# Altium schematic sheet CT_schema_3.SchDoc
size 522 x 390 mm
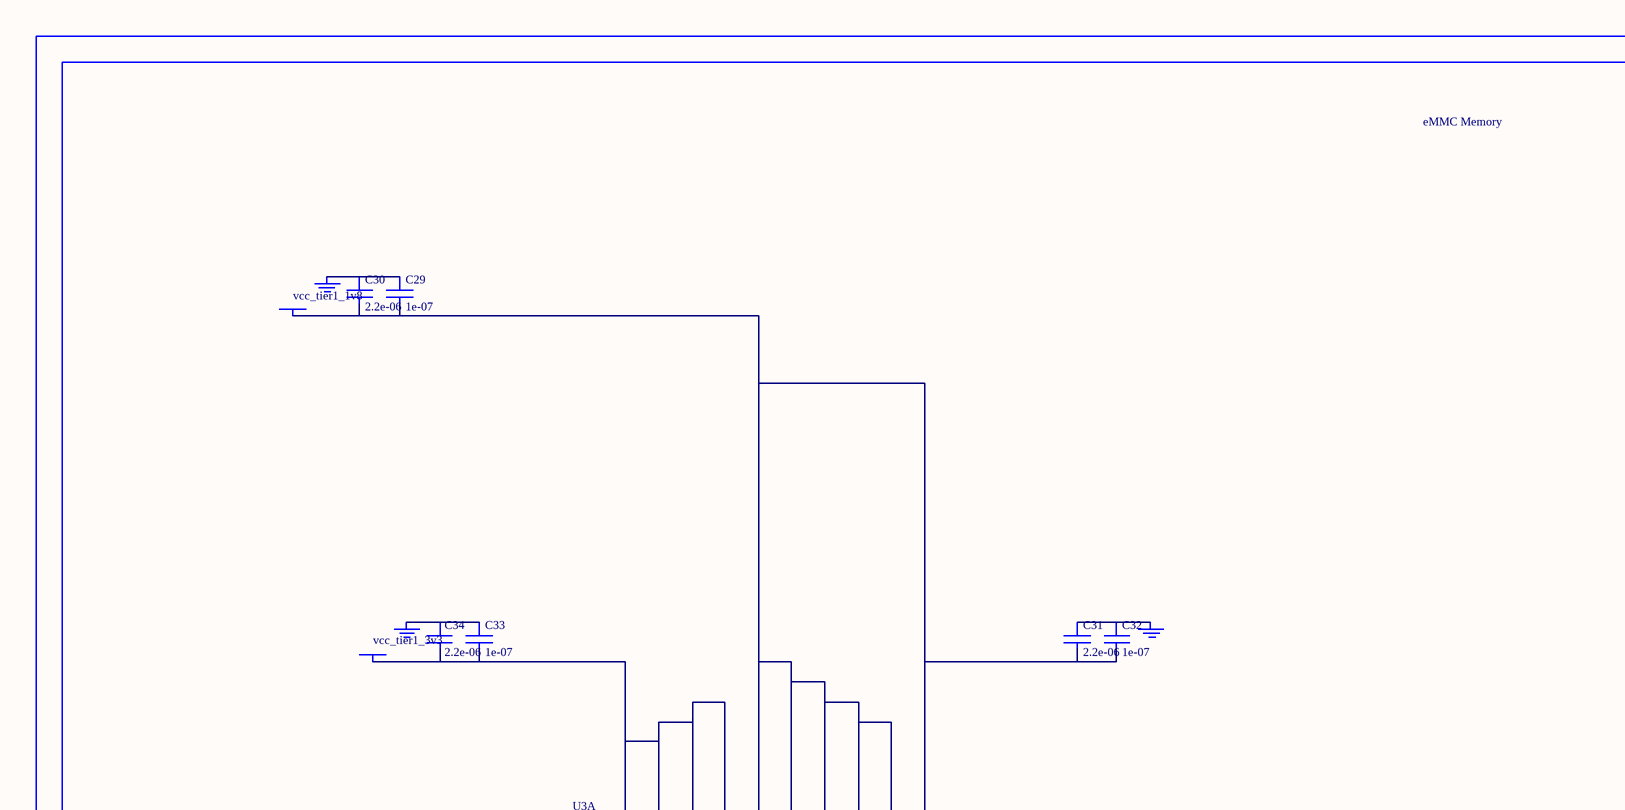
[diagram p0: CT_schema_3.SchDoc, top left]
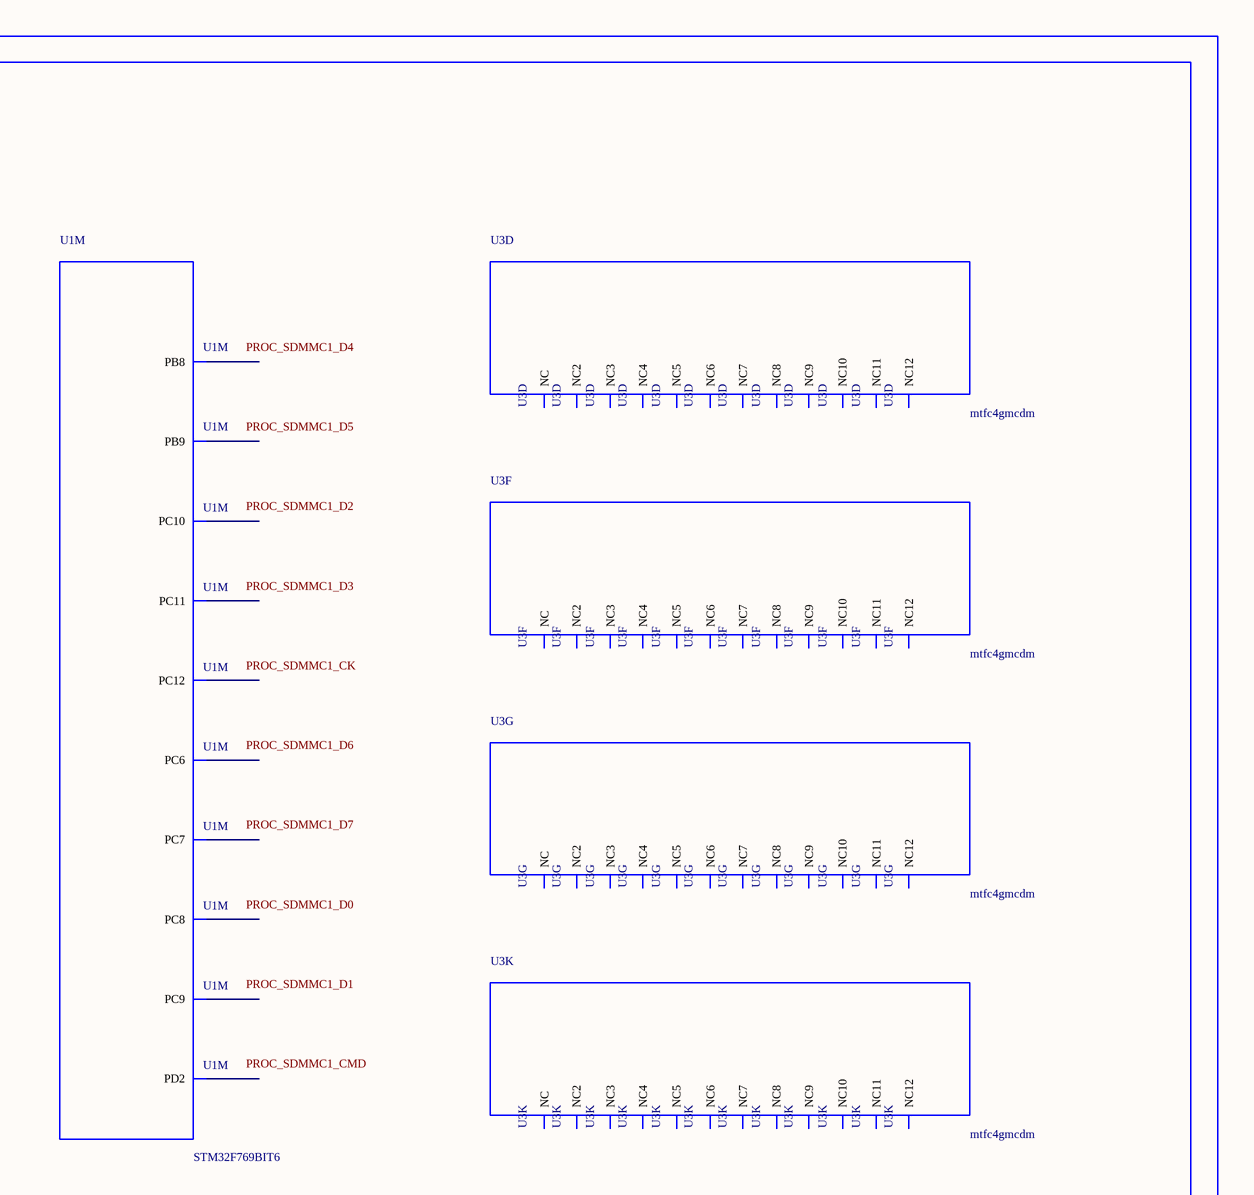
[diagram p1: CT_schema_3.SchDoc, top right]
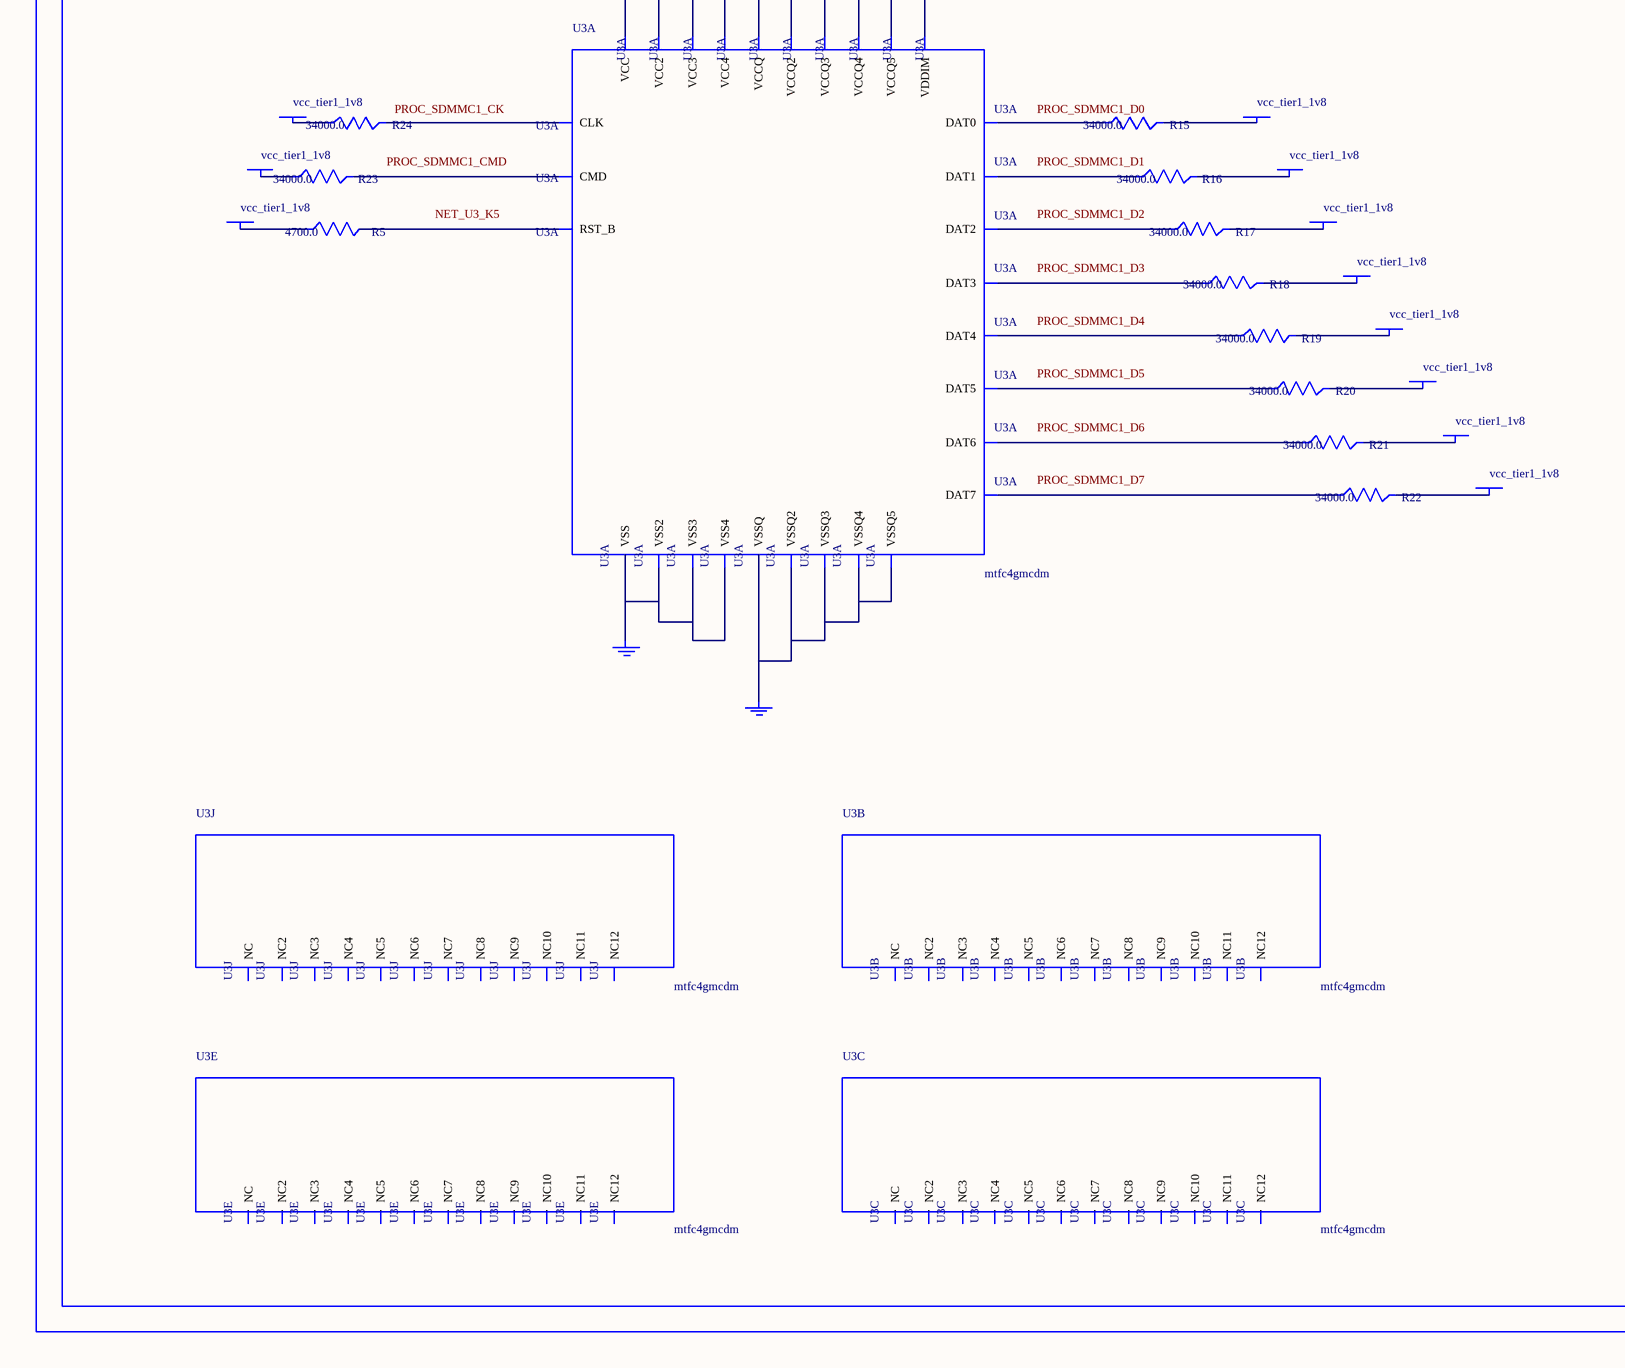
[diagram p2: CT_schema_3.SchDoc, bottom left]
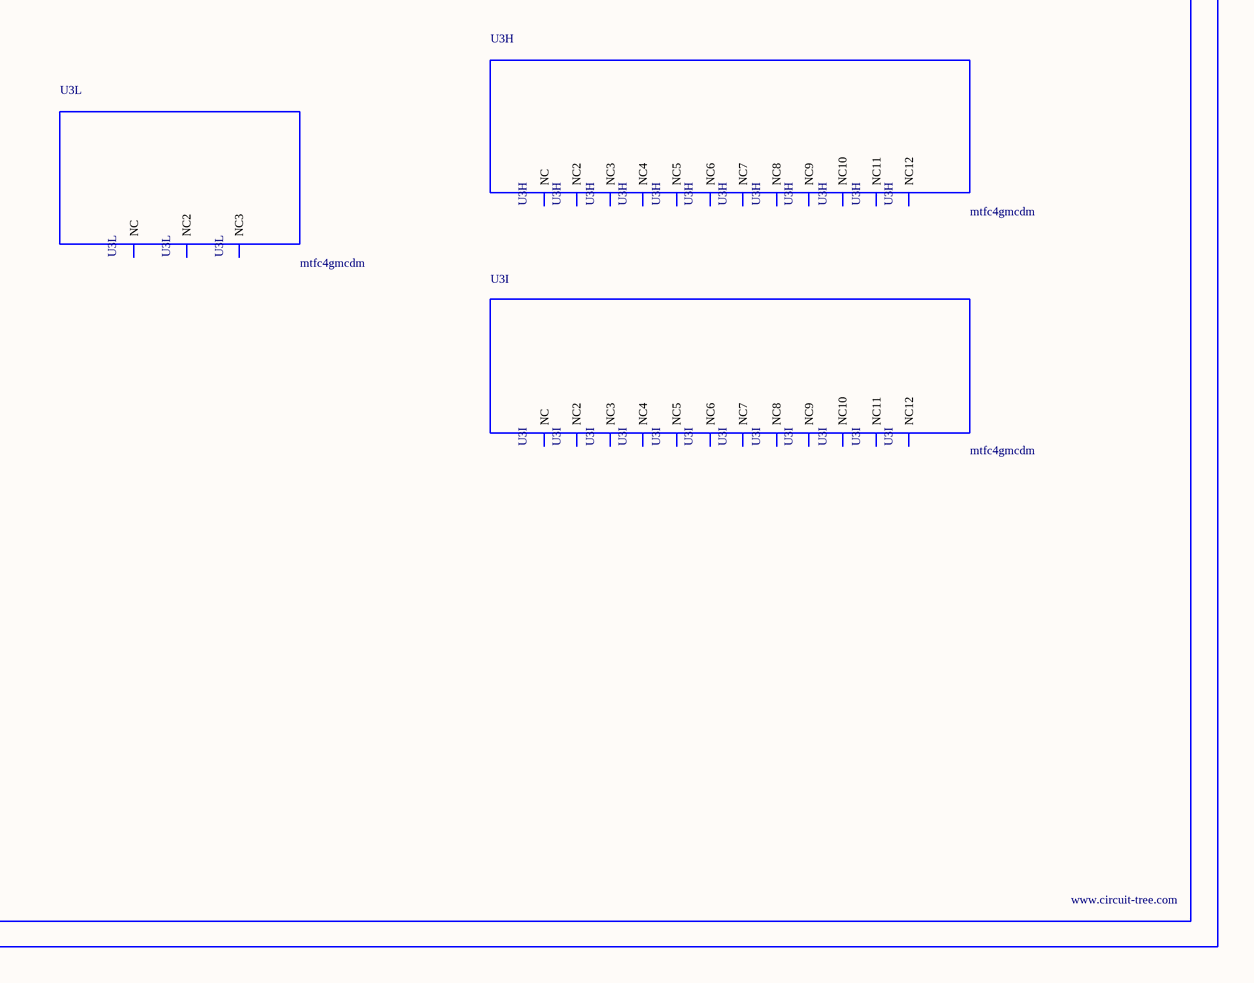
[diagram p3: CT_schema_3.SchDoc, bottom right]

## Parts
BORDER2  (no value)
C29  1e-07  [C0402]
C30  2.2e-06  [C0603]
C31  2.2e-06  [C0603]
C32  1e-07  [C0402]
C33  1e-07  [C0402]
C34  2.2e-06  [C0603]
GND_INSTANCE_2_0  (no value)
GND_INSTANCE_2_1  (no value)
GND_INSTANCE_2_2  (no value)
GND_INSTANCE_2_3  (no value)
GND_INSTANCE_2_4  (no value)
POWER_INSTANCE_2_0  vcc_tier1_1v8
POWER_INSTANCE_2_1  vcc_tier1_3v3
POWER_INSTANCE_2_2  vcc_tier1_1v8
POWER_INSTANCE_2_3  vcc_tier1_1v8
POWER_INSTANCE_2_4  vcc_tier1_1v8
POWER_INSTANCE_2_5  vcc_tier1_1v8
POWER_INSTANCE_2_6  vcc_tier1_1v8
POWER_INSTANCE_2_7  vcc_tier1_1v8
POWER_INSTANCE_2_8  vcc_tier1_1v8
POWER_INSTANCE_2_9  vcc_tier1_1v8
POWER_INSTANCE_2_10  vcc_tier1_1v8
POWER_INSTANCE_2_11  vcc_tier1_1v8
POWER_INSTANCE_2_12  vcc_tier1_1v8
R5  4700.0  [R0603]
R15  34000.0  [R0603]
R16  34000.0  [R0603]
R17  34000.0  [R0603]
R18  34000.0  [R0603]
R19  34000.0  [R0603]
R20  34000.0  [R0603]
R21  34000.0  [R0603]
R22  34000.0  [R0603]
R23  34000.0  [R0603]
R24  34000.0  [R0603]
U1  STM32F769BIT6  [LQFP208]  (part M of 15)
U3  mtfc4gmcdm  [TFBGA-153]  (parts A,B,C,D,E,F,G,H,I,J,K,L of 12)

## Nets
NetC29_1: C29.1 C30.1 GND_INSTANCE_2_0.0(GND)
NetC29_2: C29.2 C30.2 C31.2 C32.2 POWER_INSTANCE_2_0.0(PWR) U3.C2(VDDIM) U3.C6(VCCQ) U3.M4(VCCQ2) U3.N4(VCCQ3) U3.P3(VCCQ4) U3.P5(VCCQ5)
NetC31_1: C31.1 C32.1 GND_INSTANCE_2_1.0(GND)
NetC33_1: C33.1 C34.1 GND_INSTANCE_2_2.0(GND)
NetC33_2: C33.2 C34.2 POWER_INSTANCE_2_1.0(PWR) U3.E6(VCC) U3.F5(VCC2) U3.J10(VCC3) U3.K9(VCC4)
NetGND_INSTANCE_2_3_0: GND_INSTANCE_2_3.0(GND) U3.E7(VSS) U3.G5(VSS2) U3.H10(VSS3) U3.K8(VSS4)
NetGND_INSTANCE_2_4_0: GND_INSTANCE_2_4.0(GND) U3.C4(VSSQ) U3.N2(VSSQ2) U3.N5(VSSQ3) U3.P4(VSSQ4) U3.P6(VSSQ5)
NetPOWER_INSTANCE_2_2_0: POWER_INSTANCE_2_2.0(PWR) R15.2
NetPOWER_INSTANCE_2_3_0: POWER_INSTANCE_2_3.0(PWR) R16.2
NetPOWER_INSTANCE_2_4_0: POWER_INSTANCE_2_4.0(PWR) R17.2
NetPOWER_INSTANCE_2_5_0: POWER_INSTANCE_2_5.0(PWR) R18.2
NetPOWER_INSTANCE_2_6_0: POWER_INSTANCE_2_6.0(PWR) R19.2
NetPOWER_INSTANCE_2_7_0: POWER_INSTANCE_2_7.0(PWR) R20.2
NetPOWER_INSTANCE_2_8_0: POWER_INSTANCE_2_8.0(PWR) R21.2
NetPOWER_INSTANCE_2_9_0: POWER_INSTANCE_2_9.0(PWR) R22.2
NetPOWER_INSTANCE_2_10_0: POWER_INSTANCE_2_10.0(PWR) R23.1
NetPOWER_INSTANCE_2_11_0: POWER_INSTANCE_2_11.0(PWR) R24.1
NetPOWER_INSTANCE_2_12_0: POWER_INSTANCE_2_12.0(PWR) R5.1
NetR5_2: R5.2 U3.K5(RST_B)
NetR15_1: R15.1 U3.A3(DAT0)
NetR16_1: R16.1 U3.A4(DAT1)
NetR17_1: R17.1 U3.A5(DAT2)
NetR18_1: R18.1 U3.B2(DAT3)
NetR19_1: R19.1 U3.B3(DAT4)
NetR20_1: R20.1 U3.B4(DAT5)
NetR21_1: R21.1 U3.B5(DAT6)
NetR22_1: R22.1 U3.B6(DAT7)
NetR23_2: R23.2 U3.M5(CMD)
NetR24_2: R24.2 U3.M6(CLK)

Not connected (* = marked no-connect by the designer): U1 138(PC6) 139(PC7) 140(PC8) 141(PC9) 161(PC10) 162(PC11) 163(PC12) 166(PD2) 198(PB8) 199(PB9); U3 A1(NC) A2(NC7) A6(NC8) A7(NC9) A8(NC10) A9(NC11) A10(NC2) A11(NC3) A12(NC4) A13(NC5) A14(NC6) B1(NC12) B7(NC6) B8(NC7) B9(NC8) B10(NC) B11(NC2) B12(NC3) B13(NC4) B14(NC5) C1(NC9) C3(NC10) C5(NC11) C7(NC12) C8(NC6) C9(NC7) C10(NC) C11(NC2) C12(NC3) C13(NC4) C14(NC5) D1(NC8) D2(NC10) D3(NC11) D4(NC12) D12(NC9) D13(NC) D14(NC2) E1(NC3) E2(NC8) E3(NC9) E5(NC10) E8(NC11) E9(NC12) E10(NC4) E12(NC5) E13(NC6) E14(NC7) F1(NC) F2(NC6) F3(NC7) F10(NC2) F12(NC3) F13(NC4) F14(NC5) G1(NC8) G2(NC11) G3(NC12) G10(NC9) G12(NC10) G13(NC) G14(NC2) H1(NC3) H2(NC7) H3(NC8) H5(NC9) H12(NC4) H13(NC5) H14(NC6) J1(NC10) J2(NC11) J3(NC12) J5(NC4) J12(NC) J13(NC2) J14(NC3) K1(NC5) K2(NC9) K3(NC10) K6(NC11) K7(NC12) K10(NC6) K12(NC7) K13(NC8) K14(NC) L1(NC2) L2(NC6) L3(NC7) L12(NC3) L13(NC4) L14(NC5) M1(NC8) M2(NC9) M3(NC10) M7(NC11) M8(NC12) M9(NC6) M10(NC) M11(NC2) M12(NC3) M13(NC4) M14(NC5) N1(NC7) N3(NC8) N6(NC9) N7(NC10) N8(NC11) N9(NC12) N10(NC) N11(NC2) N12(NC3) N13(NC4) N14(NC5) P1(NC6) P2(NC9) P7(NC10) P8(NC11) P9(NC12) P10(NC7) P11(NC8) P12(NC) P13(NC2) P14(NC3)

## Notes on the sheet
- Labels drawn without touching a wire or pin: NET_U3_K5, PROC_SDMMC1_CK, PROC_SDMMC1_CMD, PROC_SDMMC1_D0, PROC_SDMMC1_D1, PROC_SDMMC1_D2, PROC_SDMMC1_D3, PROC_SDMMC1_D4, PROC_SDMMC1_D5, PROC_SDMMC1_D6, PROC_SDMMC1_D7

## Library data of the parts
BORDER2 = BORDER_PAGE2
C29 C32 C33 = C0402C104K3RACTU
C30 C31 C34 = C0603C225K8RACTU
GND_INSTANCE_2_0-GND_INSTANCE_2_4 = GND
POWER_INSTANCE_2_0-POWER_INSTANCE_2_12 = PWR
R5 = RC0603JR-074K7L
R15-R24 = ERA3ARB3402V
